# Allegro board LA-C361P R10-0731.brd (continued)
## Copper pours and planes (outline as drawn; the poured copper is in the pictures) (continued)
U2_PHASE1 on IN1 (solid shape): 172.31,105.96 172.31,105.64 172.05,105.39 170.15,105.39 169.96,105.58 169.96,105.95 170.1,106.09 172.18,106.09
U2_PHASE1 on IN1 (solid shape): 174.85,111.42 174.85,110.86 174.69,110.7 173.85,110.7 173.61,110.94 173.1,110.94 172.87,110.71 172.87,110.02 172.77,109.91 171.95,109.91 171.83,110.03 171.83,111.07 172.47,111.71 174.56,111.71
U2_PHASE2 on BOTTOM (solid shape): 176.02,119.13 176.02,118.31 175.83,118.12 174.24,118.12 173.99,118.37 173.99,119.07 174.18,119.26 175.9,119.26
U2_PHASE2 on BOTTOM (solid shape): 171.48,111.5 171.48,109.9 171.3,109.73 170.87,109.73 170.26,109.12 170.26,108.86 170.16,108.76 169.22,108.76 169.17,108.81 169.17,108.96 169.8,109.6 169.8,110.21 170.24,110.64 170.24,111.63 170.31,111.71 171.28,111.71
U2_PHASE2 on IN6 (solid shape): 171.36,111.35 171.36,110.5 171.15,110.3 170.33,110.3 170.18,110.45 170.18,111.33 170.37,111.51 171.2,111.51
U2_PHASE2 on IN6 (solid shape): 176.2,118.65 176.2,118.4 175.71,117.91 175.38,117.91 175.09,118.2 174.54,118.2 174,118.74 174,119 174.29,119.29 175.56,119.29
U2_PHASE3 on BOTTOM (solid shape): 175.73,103.65 175.73,103.35 175.51,103.13 173.8,103.13 173.61,103.32 173.61,103.67 173.8,103.86 175.51,103.86
U2_PHASE3 on BOTTOM (solid shape): 172.79,100.59 172.79,99.63 172.91,99.51 172.91,98.2 172.85,98.14 172.7,98.14 172.64,98.19 172.64,99.02 172.34,99.32 172.09,99.32 171.77,99.64 171.77,100.54 171.84,100.61 172.77,100.61
U2_PHASE3 on IN6 (solid shape): 174.75,103.77 174.75,103.26 174.53,103.04 173.58,103.04 172.72,102.18 172.72,99.77 172.95,99.54 172.95,99.21 172.74,99.01 171.9,99.01 171.7,99.2 171.7,102.82 172.78,103.89 174.63,103.89
U2_UGATE1 on BOTTOM (solid shape): 168.61,106.12 168.61,105.1 168.81,104.9 168.81,103.96 168.74,103.88 168.43,103.88 168.33,103.99 168.33,106.12 168.41,106.2 168.53,106.2
U2_UGATE1 on BOTTOM (solid shape): 175.79,109.93 175.79,109.51 175.63,109.36 175.07,109.36 174.56,108.85 174.18,108.85 174.05,108.97 174.05,109.83 174.33,110.1 175.62,110.1
U2_UGATE1 on IN1 (solid shape): 175.01,109.86 175.01,108.2 174.89,108.09 174.14,108.09 174,108.23 174,109.85 174.15,109.99 174.88,109.99
U2_UGATE1 on IN1 (solid shape): 169.01,104.97 169.01,104.34 169.18,104.16 169.59,104.16 169.71,104.05 169.71,103.3 169.53,103.12 168.68,103.12 168.31,103.49 168.31,104.92 168.43,105.04 168.94,105.04
U2_UGATE2 on BOTTOM (solid shape): 175.99,117.39 175.99,116.94 175.83,116.79 174.12,116.79 173.93,116.98 173.93,117.42 174.05,117.55 175.83,117.55
U2_UGATE2 on BOTTOM (solid shape): 168.74,111.43 168.74,110.21 168.61,110.08 168.61,109.17 168.53,109.09 168.41,109.09 168.33,109.17 168.33,110.46 168.26,110.54 168.26,111.38 168.38,111.5 168.66,111.5
U2_UGATE2 on IN6 (solid shape): 175.01,117.67 175.01,116.91 174.88,116.79 173.23,116.79 173.23,117.8 174.88,117.8
U2_UGATE2 on IN6 (solid shape): 169.8,112.45 169.8,111.81 169.26,111.27 169.26,110.76 168.91,110.41 168.33,110.41 168.15,110.59 168.15,111.88 168.83,112.56 169.69,112.56
U2_UGATE3 on BOTTOM (solid shape): 173.42,100.11 173.42,99.89 173.61,99.7 173.61,99.2 173.42,99.01 173.42,98.22 173.34,98.14 173.18,98.14 173.1,98.22 173.1,99.51 172.92,99.69 172.92,100.09 173.03,100.2 173.33,100.2
U2_UGATE3 on BOTTOM (solid shape): 175.2,102.62 175.52,102.62 175.72,102.42 175.72,102.07 175.51,101.86 174.88,101.86 174.56,102.18 173.74,102.18 173.62,102.29 173.62,102.76 173.74,102.88 174.95,102.88
U2_UGATE3 on IN6 (solid shape): 174.75,102.75 174.75,100.08 173.8,99.13 173.27,99.13 173.12,99.28 173.12,99.67 172.93,99.86 172.93,100.06 173.61,100.74 173.61,102.75 173.74,102.88 174.63,102.88
UG_3V on TOP (solid shape): 330.69,22.61 330.69,20.92 330.6,20.84 330.07,20.84 329.88,21.03 329.88,22.61 330.01,22.74 330.55,22.74
UG_3V on TOP (solid shape): 343.7,22.26 343.7,21.33 343.66,21.29 343.55,21.29 343.45,21.39 343.45,22.01 343.35,22.11 343.09,22.11 342.46,22.74 342.46,22.93 342.58,23.06 342.9,23.06
UG_3V on IN1 (solid shape): 331.92,22.55 331.92,21.6 331.79,21.47 329.88,21.47 329.82,21.54 329.82,22.74 330.01,22.93 331.53,22.93
UG_3V on IN1 (solid shape): 343.47,23.25 343.47,22.23 343.35,22.11 342.77,22.11 341.76,23.12 341.76,23.44 342.33,24.01 342.71,24.01
UG_5V on TOP (solid shape): 332.3,10.99 332.3,9.98 332.11,9.79 331.03,9.79 330.84,9.98 330.84,10.99 330.96,11.12 332.17,11.12
UG_5V on TOP (solid shape): 343.71,19.28 343.71,18.37 343.63,18.3 342.33,18.3 342.27,18.36 342.27,18.68 342.46,18.87 343.41,18.87 343.47,18.93 343.47,19 343.47,19 343.47,19.25 343.53,19.31 343.68,19.31
UG_5V on IN1 (solid shape): 333.63,11.18 333.44,10.99 333.19,10.99 332.11,9.91 331.66,9.91 331.47,10.11 331.47,11.25 332.11,11.88 333.63,11.88
UG_5V on IN1 (solid shape): 344.3,17.92 344.3,17.15 343.98,16.84 343.73,16.84 342.71,17.85 342.52,17.85 342.2,18.17 342.2,18.61 342.39,18.8 343.41,18.8
VCORE_B+ on TOP (solid shape): 143.13,106.56 143.13,105.67 142.88,105.42 142.11,105.42 141.86,105.67 141.86,106.56 141.99,106.69 143,106.69
VCORE_B+ on TOP (solid shape): 140.21,119.95 140.21,117.07 140.34,116.94 140.75,116.94 140.93,116.76 140.93,114.67 140.63,114.37 139.25,114.37 138.79,114.83 138.79,116.91 138.55,117.15 137.85,117.15 137.35,117.65 137.35,119.89 137.77,120.31 139.85,120.31
VCORE_B+ on TOP (solid shape): 140.08,112.78 140.08,111.19 140.85,110.43 140.85,108.32 140.82,108.29 140.82,107.9 140.74,107.82 139.32,107.82 138.69,108.46 138.69,110.24 138.59,110.34 138.59,112.64 138.77,112.82 138.9,112.81 139.02,112.86 140.01,112.86
VCORE_B+ on TOP (solid shape): 162.18,118.37 162.18,117.17 161.99,116.98 161.23,116.98 160.97,116.72 159.8,116.72 159.15,116.08 159.15,115.62 159,115.46 156.33,115.46 156.21,115.58 156.21,116.47 156.08,116.59 155.45,116.59 155.32,116.72 155.32,117.1 155.68,117.46 156.49,117.46 157.4,118.37 158.94,118.37 159.26,118.69 161.86,118.69
VCORE_B+ on BOTTOM (solid shape): 143.08,106.46 143.08,105.24 142.9,105.06 142.39,105.06 141.89,105.57 141.89,106.33 142.14,106.59 142.95,106.59
VCORE_B+ on BOTTOM (solid shape): outline of 140 points within 126.39,107.11 140.91,119.39
VCORE_B+ on IN6 (solid shape): 162.43,118.5 162.43,117.74 161.84,117.14 161.76,117.14 161.7,117.08 161.49,117.08 160.68,116.26 159.64,116.26 158.85,115.48 156.19,115.48 155.98,115.68 155.98,116.9 156.19,117.1 158.6,117.1 159.06,117.56 159.06,118.7 159.21,118.86 162.08,118.86
VCORE_B+ on IN6 (solid shape): 140.18,119.08 140.18,117.97 140.84,117.31 140.84,114.46 140.67,114.28 140.44,114.28 140.36,114.21 140.36,113.37 140.3,113.17 140.36,112.96 140.36,112.86 140.46,112.76 140.46,112.68 140.21,112.43 140.21,111.44 140.84,110.8 140.84,108.09 140.56,107.81 139.62,107.81 139.32,108.11 139.32,110.58 138.91,110.98 138.91,112.12 139.94,113.15 139.94,113.31 140.08,113.45 140.08,114.21 139.98,114.31 139.57,114.31 139.4,114.49 139.4,116.37 139.45,116.42 139.45,116.62 138.71,117.36 138.23,117.36 137.54,118.04 137.54,119.11 137.8,119.36 139.9,119.36
VCORE_B+ on BOTTOM: 156.05,115.45 156.02,115.48 156.02,115.9 155.93,115.99 155.39,115.99 155.3,116.07 155.3,116.19 155.39,116.28 155.96,116.28 156.03,116.35 156.03,116.97 156.06,117 158.62,117 159.26,117.64 159.26,118.07 159.54,118.35 162.33,118.35 162.43,118.25 162.43,117.36 162.12,117.04 161.48,117.04 161.27,116.82 161.26,116.82 160.64,116.2 159.62,116.2 159.04,115.62 159.04,115.48 159.02,115.45
VCORE_B+ on IN4: outline of 236 points within 136.91,105.47 162.37,119.64
VSB_N_001 on TOP: 30.74,17.53 31.56,17.53 31.81,17.28 31.81,16.52 31.94,16.39 32.58,16.39 32.7,16.26 32.7,16.01 32.89,15.82 32.89,15.5 32.77,15.38 32.01,15.38 30.86,16.52 30.74,16.52 30.67,16.58 30.67,17.47
N13272521 on TOP (solid shape): 108.84,61.48 108.84,60.46 108.65,60.27 106.81,60.27 106.68,60.4 106.68,61.03 106.74,61.1 107.63,61.1 108.08,61.54 108.78,61.54
N17034092 on TOP (solid shape): 341.2,22.23 341.2,21.57 341.22,21.57 341.65,21.14 342.04,21.14 342.34,20.84 343.35,20.84 343.41,20.78 343.41,20.64 343.37,20.6 342.31,20.6 342.21,20.7 342.07,20.7 342.07,20.7 341.12,20.7 341.08,20.66 340.32,20.66 340.22,20.76 340.22,22.23 340.34,22.35 341.08,22.35
N19849916 on TOP (solid shape): 244.92,56.27 244.92,55.44 244.86,55.38 242.57,55.38 242.44,55.51 242.44,56.27 242.57,56.4 244.79,56.4
N19912586 on TOP (solid shape): 185.6,117.76 185.6,114.69 185.22,114.31 182.25,114.31 181.67,114.88 181.67,116.59 181.77,116.69 181.77,117.26 181.99,117.48 182.88,117.48 183.64,118.25 185.12,118.25
N19912586 on BOTTOM (solid shape): 186.23,118.65 186.23,112.99 185.6,112.35 184,112.35 183.36,112.99 183.36,113.64 182.75,114.25 180.56,114.25 180.44,114.37 180.44,117.36 180.63,117.55 182.91,117.55 183.22,117.86 183.24,117.86 183.29,117.92 183.29,118.68 183.57,118.96 185.93,118.96
N19912586 on IN1 (solid shape): 186.21,118.65 186.21,113.04 185.55,112.38 184,112.38 183.38,113 183.38,113.27 183.36,113.28 183.36,113.65 182.75,114.26 180.62,114.26 180.47,114.41 180.47,117.33 180.67,117.53 182.53,117.53 183.26,118.27 183.26,118.65 183.64,119.03 185.83,119.03
N19912586 on IN2 (solid shape): 186.21,118.68 186.21,112.91 185.62,112.33 184.05,112.33 183.39,112.99 183.39,113.57 182.7,114.26 180.6,114.26 180.42,114.44 180.42,117.33 180.62,117.53 182.86,117.53 183.29,117.97 183.29,118.68 183.57,118.96 185.93,118.96
N19912586 on IN4 (solid shape): 186.26,118.65 186.26,112.99 185.62,112.35 183.97,112.35 183.36,112.96 183.36,113.62 182.73,114.26 180.57,114.26 180.44,114.39 180.44,117.33 180.65,117.53 182.86,117.53 183.26,117.94 183.29,117.94 183.29,118.7 183.54,118.96 185.95,118.96
N19912586 on IN5 (solid shape): 186.23,118.65 186.23,112.99 185.6,112.35 184,112.35 183.34,113.01 183.34,113.65 182.73,114.26 180.6,114.26 180.42,114.44 180.42,117.31 180.65,117.53 182.86,117.53 183.29,117.97 183.29,118.68 183.57,118.96 185.93,118.96
N48708347 on BOTTOM (solid shape): 283.53,29.09 283.53,26.87 283.47,26.81 282.77,26.81 282.7,26.87 282.7,29.03 282.83,29.16 283.47,29.16
N52699143 on TOP (solid shape): 33.66,5.03 33.66,2.2 33.37,1.91 32.64,1.91 32.32,2.23 32.32,5.03 32.51,5.22 33.47,5.22
N110703687 on TOP (solid shape): 181.23,109.48 181.23,107.9 181.02,107.69 180.17,107.69 179.9,107.96 178.82,107.96 178.75,108.02 178.75,109.04 178.82,109.1 179.64,109.1 180.09,109.55 181.17,109.55
N110833422 on TOP (solid shape): 185.52,109.66 185.52,106.13 185.22,105.83 182.65,105.83 181.45,107.03 181.45,107.93 181.42,107.96 181.42,109.85 181.71,110.14 185.04,110.14
N110833422 on BOTTOM (solid shape): 186.27,111.2 186.27,104.8 185.54,104.06 183.17,104.06 182.67,104.56 182.67,105.51 181.43,106.75 180.44,106.75 180.31,106.88 180.31,109.86 180.5,110.05 182.75,110.05 184.21,111.51 185.95,111.51
N110833422 on IN1 (solid shape): 186.26,111.08 186.26,104.89 186.25,104.87 186.25,104.77 185.6,104.12 183.44,104.12 182.83,104.73 182.83,105.6 181.66,106.77 180.62,106.77 180.39,106.99 180.39,109.91 180.54,110.07 182.78,110.07 184.07,111.36 185.98,111.36
N110833422 on IN2 (solid shape): 186.26,111.08 186.26,104.89 186.25,104.87 186.25,104.77 185.6,104.12 183.44,104.12 182.83,104.73 182.83,105.6 181.66,106.77 180.62,106.77 180.39,106.99 180.39,109.91 180.54,110.07 182.78,110.07 184.07,111.36 185.98,111.36
N110833422 on IN4 (solid shape): 186.26,111.08 186.26,104.89 186.25,104.87 186.25,104.77 185.6,104.12 183.44,104.12 182.83,104.73 182.83,105.6 181.66,106.77 180.62,106.77 180.39,106.99 180.39,109.91 180.54,110.07 182.78,110.07 184.07,111.36 185.98,111.36
N110833422 on IN5 (solid shape): 186.26,111.08 186.26,104.89 186.25,104.87 186.25,104.77 185.6,104.12 183.44,104.12 182.83,104.73 182.83,105.6 181.66,106.77 180.62,106.77 180.39,106.99 180.39,109.91 180.54,110.07 182.78,110.07 184.07,111.36 185.98,111.36
N110836828 on TOP (solid shape): 180.91,101.8 180.91,100.21 180.72,100.02 179.96,100.02 179.58,100.4 178.75,100.4 178.63,100.53 178.63,101.42 178.75,101.55 179.45,101.55 179.83,101.93 180.79,101.93
N110836908 on TOP (solid shape): 185.59,102.54 185.59,100.38 185.29,100.08 181.67,100.08 181.48,100.28 181.48,101.74 181.5,101.75 181.5,102.48 181.79,102.78 185.34,102.78
N110836908 on BOTTOM (solid shape): 186.28,103.03 186.28,99.91 184.74,98.36 184.74,98.03 184.68,97.98 181.92,97.98 180.57,99.32 180.34,99.32 180.21,99.45 180.21,102.43 180.4,102.62 182.58,102.62 183.36,103.41 185.9,103.41
N110836908 on IN1 (solid shape): 186.18,102.98 186.18,99.81 184.81,98.43 181.51,98.43 180.32,99.63 180.32,102.35 180.49,102.52 182.5,102.52 183.34,103.36 185.8,103.36
N110836908 on IN2 (solid shape): 186.18,102.98 186.18,99.81 184.81,98.43 181.51,98.43 180.32,99.63 180.32,102.35 180.49,102.52 182.5,102.52 183.34,103.36 185.8,103.36
N110836908 on IN4 (solid shape): 186.18,102.98 186.18,99.81 184.81,98.43 181.51,98.43 180.32,99.63 180.32,102.35 180.49,102.52 182.5,102.52 183.34,103.36 185.8,103.36
N110836908 on IN5 (solid shape): 186.18,102.98 186.18,99.81 184.81,98.43 181.51,98.43 180.32,99.63 180.32,102.35 180.49,102.52 182.5,102.52 183.34,103.36 185.8,103.36
N110935541 on BOTTOM (solid shape): 171.25,102.95 171.25,102.19 171.23,102.17 168.92,102.17 168.9,102.19 168.9,102.83 169.11,103.03 171.17,103.03
N110936515 on BOTTOM (solid shape): 171.51,113.04 171.51,112.4 171.32,112.21 169.1,112.21 168.95,112.37 168.95,113.09 169.09,113.23 171.32,113.23
N110936976 on BOTTOM (solid shape): 174.5,101.99 174.5,101.35 174.44,101.29 171.83,101.29 171.77,101.35 171.77,101.99 171.83,102.05 174.44,102.05
N111796536 on TOP (solid shape): 312.6,33.87 312.6,33.22 311.28,31.9 309.88,31.9 309.86,31.92 309.86,32.83 309.89,32.86 310.85,32.86 311.93,33.95 312.51,33.95
N111796622 on TOP (solid shape): 312.64,37.46 312.64,36.53 312.59,36.49 312.59,35.35 312.54,35.3 311.63,35.3 311.56,35.37 311.56,36.25 311.9,36.59 311.9,37.42 312.02,37.54 312.56,37.54
N116494866 on TOP (solid shape): 237.51,53.23 237.55,53.15 237.55,51.29 237.4,51.14 236.39,51.14 235.87,51.66 235.14,51.66 235.01,51.79 235.01,52.96 235.05,53.04 235.14,53.06 235.53,52.99 235.92,52.96 236.68,53.03 237.41,53.24
N116496514 on TOP (solid shape): 181.42,116.72 181.42,115.13 181.23,114.94 180.47,114.94 180.15,115.26 179.52,115.26 179.32,115.45 179.32,116.4 179.39,116.47 180.02,116.47 180.4,116.85 181.29,116.85
N119009632 on BOTTOM (solid shape): 17.75,69.7 17.75,69.33 17.48,69.06 17.48,68.58 17.04,68.14 16.75,68.14 16.59,68.29 16.59,69.61 16.81,69.83 17.62,69.83
N119942216 on BOTTOM (solid shape): 27.7,79.11 27.7,78.09 27.27,77.65 27.27,76.7 26.59,76.01 26.59,75.5 26.52,75.43 24.57,75.43 24.33,75.19 24.33,70.28 24.2,70.14 20.46,70.14 20.4,70.2 20.4,76.69 24.64,76.69 24.64,76.64 24.65,76.59 24.66,76.54 24.69,76.49 24.72,76.44 24.75,76.4 24.79,76.37 24.84,76.34 24.89,76.33 24.94,76.31 25,76.31 25.05,76.31 25.1,76.33 25.15,76.34 25.2,76.37 25.24,76.4 25.27,76.44 25.3,76.49 25.33,76.54 25.34,76.59 25.35,76.64 25.35,76.69 25.34,76.75 25.33,76.8 25.3,76.84 25.27,76.89 25.24,76.93 25.2,76.96 25.15,76.99 25.1,77.01 25.05,77.02 25,77.02 24.94,77.02 24.89,77.01 24.84,76.99 24.79,76.96 24.75,76.93 24.72,76.89 24.69,76.84 24.66,76.8 24.65,76.75 24.64,76.69 20.4,76.69 20.4,78.05 20.72,78.37 21.46,78.37 22.25,79.15 22.46,79.15 22.48,79.18 27.64,79.18
N119944438 on TOP (solid shape): 53.35,16 53.45,16 53.51,15.95 53.51,15.39 52.16,14.04 51.37,14.04 51.18,13.85 51.18,13.34 51.06,13.22 50.8,13.22 50.67,13.34 50.67,13.98 50.74,14.04 50.74,15.34 50.86,15.47 52.29,15.47 52.64,15.82 52.64,15.95 52.71,16.01 53.34,16.01
N119965248 on BOTTOM (solid shape): 27.26,68.67 27.35,68.34 27.51,68.03 27.52,68.01 27.52,67.21 27.41,67.09 27.41,66.8 27.34,66.72 27.29,66.63 27.29,66.61 27.17,66.49 25.66,66.49 24.92,65.76 24.92,64.83 24.63,64.54 23.42,64.54 22.99,64.97 22.61,64.97 22.47,65.1 22.47,65.48 22.73,65.74 23.1,65.74 24.14,66.78 24.17,66.78 24.17,66.81 24.37,67.01 24.66,67.01 24.68,67.03 24.7,67.03 24.83,67.12 24.91,67.25 24.92,67.27 25.01,67.36 25.01,67.45 26.43,67.45 26.79,67.8 26.43,68.16 25.01,68.16 25.01,68.66 25.08,68.73 27.25,68.73
N119965290 on BOTTOM (solid shape): 25.55,65.62 25.55,64.98 25.71,64.83 26.04,64.83 26.12,64.74 26.12,64.72 26.14,64.7 26.14,64.37 26.06,64.3 25.9,64.3 25.89,64.31 25.32,64.31 25.15,64.47 25.15,65.64 25.26,65.74 25.43,65.74
N120361841 on TOP (solid shape): 59.25,3.18 59.25,2.68 58.8,2.23 57.21,2.23 56.96,2.49 56.96,3.25 57.02,3.31 59.12,3.31
N120970730 on TOP (solid shape): 150.05,101.74 150.05,100.66 149.42,100.02 147,100.02 146.75,100.28 146.75,101.06 146.97,101.28 147,101.28 147.65,101.93 149.86,101.93
N120971346 on BOTTOM (solid shape): 148.34,117.96 148.34,117.69 148.54,117.48 149.23,117.48 149.29,117.42 149.29,116.47 149.1,116.28 147.26,116.28 147.11,116.42 147.11,117.97 147.23,118.09 148.21,118.09
N120971480 on TOP (solid shape): 161.8,111.71 161.8,109.67 161.56,109.43 159.95,109.43 159.83,109.55 159.83,110.5 159.96,110.63 160.78,110.63 160.85,110.69 160.85,111.64 161.04,111.83 161.67,111.83
N120976432 on TOP (solid shape): 161.49,108.77 161.49,108.59 161.52,108.59 161.65,108.47 161.65,106.83 161.35,106.54 161.27,106.54 160.48,105.75 160.48,105.7 159.61,105.7 158.62,106.69 158.62,108.09 159.51,108.97 161.29,108.97
N120976432 on BOTTOM (solid shape): 158.67,112.94 158.67,112.54 159.27,111.95 161.11,111.95 161.32,111.74 161.32,106.29 160.91,105.88 160.86,105.88 160.71,105.72 159.36,105.72 158.95,106.14 158.93,106.17 158.93,107.17 158.65,107.45 156.02,107.45 155.7,107.77 155.7,112.47 156.05,112.81 156.05,113.04 156.24,113.23 158.38,113.23
N120976432 on IN6 (solid shape): 158.7,112.91 158.7,112.53 159.26,111.97 161.16,111.97 161.32,111.82 161.32,106.28 160.94,105.9 160.86,105.9 160.61,105.65 159.51,105.65 158.98,106.18 158.98,107.15 158.67,107.45 156.03,107.45 155.73,107.76 155.73,112.51 156.19,112.96 156.19,113.06 156.34,113.22 158.4,113.22
N120977691 on BOTTOM (solid shape): 146.56,117.93 146.56,116.44 146.56,116.37 147.24,115.68 149.25,115.68 149.4,115.53 149.4,113.78 149.05,113.42 147.96,113.42 147.73,113.19 147.73,112.33 148.34,111.72 148.34,111.31 148.03,111.01 145.06,111.01 144.97,111.1 144.97,113.93 144.4,114.5 143.19,114.5 143.13,114.56 143.13,116.59 143.13,116.62 143.17,116.66 143.97,116.66 144.46,117.15 144.46,117.99 144.53,118.06 146.43,118.06
N120977691 on IN6 (solid shape): 146.56,117.86 146.56,116.34 147.17,115.73 149.33,115.73 149.53,115.53 149.53,113.75 149.2,113.42 148.24,113.42 147.88,113.06 147.88,112.38 148.44,111.82 148.44,111.39 148.01,110.96 145.16,110.96 144.96,111.16 144.96,113.72 144.98,113.75 144.98,113.9 144.37,114.51 143.26,114.51 143.1,114.66 143.1,116.49 143.33,116.72 144.1,116.72 144.48,117.1 144.48,117.76 144.43,117.81 144.43,117.89 144.58,118.04 146.38,118.04
N121616264 on TOP (solid shape): 222.67,11.48 222.67,9.4 222.6,9.33 221.94,9.33 221.69,9.58 221.69,11.58 221.74,11.63 222.52,11.63
N121617759 on TOP: 238.69,5.15 238.2,5.63 238.2,7.37 238.25,7.43 239.71,7.43 239.8,7.34 239.8,6.83 240.89,5.74 240.89,5.2 240.84,5.15
N121617766 on TOP (solid shape): 244.3,7.39 244.3,5.5 243.96,5.16 242.31,5.16 242.27,5.2 242.27,5.86 242.72,6.32 242.72,7.4 242.84,7.51 244.17,7.51
N121795600 on TOP (solid shape): 145.82,104.02 148.53,104.02 148.65,103.89 148.65,102.74 148.43,102.51 148.41,102.51 148.15,102.24 147.52,102.24 146.79,101.51 145.52,101.51 144.93,102.09 144.93,103.97 145.24,104.28 145.57,104.28
N121795600 on BOTTOM (solid shape): 148.97,110.02 148.97,106.1 148.82,105.95 147.86,105.95 147.73,105.83 147.73,104.89 147.91,104.71 148.57,104.71 148.97,104.3 148.97,101.96 148.49,101.48 145.75,101.48 144.97,102.26 144.97,106.94 143.96,107.96 143.13,107.96 143.07,108.02 143.07,110.18 143.08,110.2 144.63,110.2 144.9,110.47 148.51,110.47
N121795600 on IN6 (solid shape): 149.05,110.14 149.05,106.1 148.87,105.93 148.21,105.93 147.8,105.52 147.8,104.96 148.06,104.71 148.59,104.71 148.95,104.35 148.95,102.07 148.51,101.63 145.8,101.63 145.78,101.65 145.56,101.65 144.86,102.35 144.86,107.1 143.99,107.96 143.08,107.96 143,108.04 143,110.02 143.18,110.19 144.58,110.19 144.96,110.58 148.62,110.58
N121994849 on TOP (solid shape): 219.66,47.28 220.56,47.28 220.6,47.24 220.6,46.62 220.54,46.55 218.38,46.55 218.31,46.62 218.31,47.38 218.38,47.44 219.5,47.44
N122017154 on BOTTOM (solid shape): 138.69,111.9 138.69,110.63 139.07,110.24 139.07,109.86 138.56,109.86 138.05,110.37 138.05,111.39 137.8,111.64 137.29,111.64 137.16,111.77 137.16,112.28 138.3,112.28
N122018016 on BOTTOM (solid shape): 139.17,116.47 139.17,116.29 139.14,116.26 138.56,116.26 138.3,116.52 138.3,116.67 137.92,117.05 137.52,117.05 137.39,117.18 137.39,117.64 137.44,117.69 137.95,117.69
N122018494 on BOTTOM (solid shape): 159.51,119.01 159.51,118.63 159.01,118.12 159.01,117.87 158.56,117.42 158.56,117.34 158.4,117.18 158.1,117.18 157.98,117.31 157.98,117.67 158.88,118.58 158.88,119.01 158.95,119.08 159.44,119.08
N122528028 on TOP: 230.46,50.28 231.39,50.28 231.47,50.2 231.47,48.43 231.04,48 228.74,48 228.06,48.68 228.06,50.15 228.35,50.44 228.73,50.44 229.25,49.92 230.1,49.92
N122536166 on TOP (solid shape): 28.35,67.22 28.35,67.03 28.53,66.86 28.53,65.7 28.58,63.96 28.71,62.24 28.72,62.21 28.72,61.74 28.58,61.6 27.66,61.6 27.06,62.21 27.06,67.2 27.2,67.34 27.56,67.34 27.66,67.45 28.13,67.45
N122536166 on BOTTOM (solid shape): 28.33,67.18 28.33,67.08 28.53,66.88 28.53,65.7 28.58,64.01 28.71,62.33 28.71,62.3 28.71,61.89 28.45,61.63 28.08,61.63 27.46,62.25 27.46,66.26 27.43,66.28 27.43,66.61 27.53,66.71 27.53,67.04 27.69,67.19 27.69,67.32 27.81,67.45 28.07,67.45
N122719762 on BOTTOM (solid shape): 18.96,60.85 18.96,60.66 18.05,59.75 18.05,57.23 17.96,57.14 17.41,57.14 17.26,57.29 17.26,58.65 17.08,58.83 17.08,60.11 17.53,60.56 17.53,60.75 17.77,60.98 18.83,60.98
N122728389 on TOP (solid shape): 25.66,14.86 25.66,11.13 25.06,10.54 25.06,9.25 24.06,8.24 22.5,8.24 21.86,7.61 21.86,6.55 21.81,6.51 20.57,6.51 20.5,6.58 20.5,7.2 22.14,8.84 23.39,8.84 23.82,9.27 23.82,10.83 24.45,11.46 24.45,14.79 24.67,15.01 25.5,15.01
N122729223 on TOP (solid shape): 27.5,14.68 27.5,13.47 28,12.96 28.89,12.96 30.01,11.85 30.01,10.25 29.89,10.13 28.87,10.13 28.2,10.8 26.16,10.8 25.91,11.06 25.91,14.87 26.04,14.99 27.18,14.99
N122754331 on TOP (solid shape): 131.99,67.26 131.99,66.61 131.93,66.54 129.5,66.54 129.41,66.63 129.41,67.24 129.53,67.36 131.89,67.36
N122755391 on BOTTOM (solid shape): 185.93,86.46 186.1,86.46 186.27,86.29 186.27,83.68 185.68,83.08 185.3,83.08 184.88,82.66 184.42,82.66 184.28,82.52 184.28,82.08 184.12,81.92 183.55,81.92 183.36,82.12 183.36,83.06 183.47,83.16 183.67,83.16 184.88,84.37 184.88,86.28 185.06,86.46 185.93,86.46
N122762967 on TOP (solid shape): 229.88,60.49 230.56,60.49 230.63,60.41 230.63,59.66 230.53,59.56 230.45,59.56 229.89,59 228.26,59 228.14,59.11 228.14,60.51 228.21,60.58 229.79,60.58
N122912247 on TOP (solid shape): 182.18,82.06 182.18,81.86 181.96,81.64 181.96,81.55 181.95,81.54 181.94,81.44 181.95,81.34 181.96,81.34 181.96,81.25 182.54,80.66 182.54,79.49 182.36,79.3 181.79,79.3 181.7,79.4 181.7,80.27 181.51,80.46 181.16,80.46 181.03,80.59 181.03,81.28 180.5,81.81 180.5,82.11 180.64,82.25 181.98,82.25
N123037911 on BOTTOM: 202.59,55.5 202.25,55.16 201.08,55.16 200.85,55.39 200.85,56 201.11,56.26 201.11,57.63 202.05,58.56 202.29,58.56 202.49,58.76 203.9,58.76 203.96,58.7 203.96,57.94 203.66,57.64 203.18,57.64 202.59,57.05
N123983992 on TOP (solid shape): 114.12,69.63 114.12,67.95 113.56,67.4 111.2,67.4 110.87,67.73 110.87,68.42 110.94,68.48 110.94,69.8 111.19,70.05 113.7,70.05
N123983992 on BOTTOM (solid shape): 108.97,74.75 109.92,74.75 110.3,74.37 113.03,74.37 113.04,74.36 114.24,74.36 114.92,73.68 114.92,71.37 114.53,70.98 113.44,70.98 113.35,70.89 113.35,69.85 113.39,69.81 114.56,69.81 114.91,69.45 114.91,66.96 114.78,66.84 111.74,66.84 110.49,68.08 110.49,71.64 109.67,72.46 108.97,72.46 108.82,72.61 108.82,74.68 108.89,74.75 108.97,74.75
N123983992 on IN3 (solid shape): 110.36,74.38 114.3,74.38 114.99,73.69 114.99,71.33 114.61,70.95 113.56,70.95 113.34,70.72 113.34,69.94 113.49,69.78 114.53,69.78 114.91,69.4 114.91,67.04 114.71,66.84 111.76,66.84 110.52,68.08 110.52,71.71 109.7,72.53 108.92,72.53 108.79,72.65 108.79,74.68 108.84,74.74 110.01,74.74
N123983992 on IN4 (solid shape): 110.36,74.38 114.3,74.38 114.99,73.69 114.99,71.33 114.61,70.95 113.56,70.95 113.34,70.72 113.34,69.94 113.49,69.78 114.53,69.78 114.91,69.4 114.91,67.04 114.71,66.84 111.76,66.84 110.52,68.08 110.52,71.71 109.7,72.53 108.92,72.53 108.79,72.65 108.79,74.68 108.84,74.74 110.01,74.74
N123983992 on IN6 (solid shape): 110.36,74.38 114.3,74.38 114.99,73.69 114.99,71.33 114.61,70.95 113.56,70.95 113.34,70.72 113.34,69.94 113.49,69.78 114.53,69.78 114.91,69.4 114.91,67.04 114.71,66.84 111.76,66.84 110.52,68.08 110.52,71.71 109.7,72.53 108.92,72.53 108.79,72.65 108.79,74.68 108.84,74.74 110.01,74.74
N123984012 on TOP (solid shape): 107.89,96.81 107.89,93.61 107.51,93.23 105.73,93.23 105.54,93.42 105.54,93.42 105.48,93.48 105.48,96.34 106.21,97.07 107.62,97.07
N123984012 on BOTTOM (solid shape): 108.91,98.06 109.66,98.06 109.66,98.6 110.11,98.6 110.11,98.07 110.81,98.07 110.82,98.06 111.23,98.06 111.41,97.88 111.41,96.85 111.22,96.66 108.46,96.66 108.14,96.34 108.14,91.64 108.08,91.58 107.63,91.58 107.55,91.66 107.55,92.15 107.33,92.37 106.56,92.37 106.47,92.46 106.47,92.97 106.18,93.26 105.62,93.26 105.48,93.4 105.48,94.14 105.28,94.34 104.84,94.34 104.79,94.39 104.79,95.65 104.97,95.83 106.1,95.83 106.55,96.29 106.55,97.1 107.51,98.06 108.46,98.06 108.46,98.6 108.91,98.6
N123984061 on BOTTOM (solid shape): 113.29,96.05 113.29,95.7 113.48,95.51 113.86,95.51 113.98,95.39 113.98,95.13 113.92,95.07 112.71,95.07 112.6,95.18 112.6,96.08 112.72,96.2 113.14,96.2
N123984061 on BOTTOM (solid shape): 109.46,94.2 109.46,90.56 109.41,90.51 109.41,87.07 108.84,86.5 104.78,86.5 104.63,86.65 104.63,88 104.77,88.15 106.74,88.15 107.06,88.46 107.06,90.43 107.7,91.07 108.08,91.07 108.4,91.39 108.4,94.19 108.42,94.21 109.45,94.21
N123984061 on IN6 (solid shape): 113.54,96.66 113.54,95.45 113.16,95.07 112.71,95.07 112.59,95.2 112.59,96.07 112.31,96.35 112.31,96.9 112.58,97.17 113.02,97.17
N123984061 on IN6 (solid shape): 109.48,92.15 109.48,90.94 109.35,90.81 108.21,90.81 108.14,90.88 108.14,91.64 108.52,92.02 108.52,92.21 108.65,92.34 109.28,92.34
N123984063 on BOTTOM (solid shape): 107.38,92.07 107.38,91.13 107.32,91.07 106.43,91.07 106.3,91.19 106.3,92.02 106.47,92.19 107.26,92.19
N123984063 on BOTTOM (solid shape): 117.41,95.89 117.41,95.26 117.35,95.2 116.27,95.2 116.14,95.07 115.44,95.07 115.38,95.13 115.38,95.83 115.51,95.96 117.35,95.96
N123984063 on IN6 (solid shape): 107.51,91.58 107.51,90.05 107.5,90.05 107.5,89.87 107.25,89.62 107.06,89.62 107.06,89.67 106.36,90.37 106.36,91.64 106.43,91.7 107.38,91.7
N123984063 on IN6 (solid shape): 117.41,95.89 117.41,95.26 117.35,95.2 116.4,95.2 116.21,95 116.21,94.24 116.02,94.05 115.7,94.05 115.41,94.34 115.41,95.61 115.83,96.02 117.29,96.02
N123984101 on BOTTOM (solid shape): 104.87,76.49 104.87,74.41 104.79,74.33 104.27,74.33 104.13,74.48 104.13,76.32 104.4,76.59 104.78,76.59
N123984161 on BOTTOM (solid shape): 106.11,91.45 106.11,90.75 106.49,90.37 106.49,89.35 106.38,89.24 104.76,89.24 104.65,89.35 104.65,91.39 104.84,91.57 105.99,91.57
N123984183 on TOP (solid shape): 115.55,81.8 115.55,80.32 115.11,79.89 110.72,79.89 110.43,80.18 110.43,81.8 110.56,81.93 110.56,81.97 111.91,83.32 114.02,83.32
N123984183 on BOTTOM (solid shape): 115.83,84.01 115.83,83.32 115.65,83.14 114.38,83.14 114.25,83.02 114.25,82.15 114.51,81.9 115.65,81.9 115.83,81.72 115.83,79.82 115.65,79.64 110.94,79.64 110.57,80 109.81,80 109.54,80.27 109.54,82.37 109.73,82.56 110.57,82.56 111.06,83.05 111.06,83.83 111.32,84.08 112.52,84.08 113.01,84.57 115.27,84.57
N123984183 on IN3 (solid shape): 115.83,84.01 115.83,83.32 115.65,83.14 114.38,83.14 114.25,83.02 114.25,82.15 114.51,81.9 115.24,81.9 115.52,81.62 115.52,79.79 115.37,79.64 110.94,79.64 110.57,80 109.81,80 109.54,80.27 109.54,82.37 109.73,82.56 110.57,82.56 111.06,83.05 111.06,83.83 111.32,84.08 112.52,84.08 113.01,84.57 115.27,84.57
N123984183 on IN4 (solid shape): 115.83,84.01 115.83,83.32 115.65,83.14 114.38,83.14 114.25,83.02 114.25,82.15 114.51,81.9 115.24,81.9 115.52,81.62 115.52,79.79 115.37,79.64 110.94,79.64 110.57,80 109.81,80 109.54,80.27 109.54,82.37 109.73,82.56 110.57,82.56 111.06,83.05 111.06,83.83 111.32,84.08 112.52,84.08 113.01,84.57 115.27,84.57
N123984183 on IN6 (solid shape): 115.83,84.01 115.83,83.32 115.65,83.14 114.38,83.14 114.25,83.02 114.25,82.15 114.51,81.9 115.24,81.9 115.52,81.62 115.52,79.79 115.37,79.64 110.94,79.64 110.57,80 109.81,80 109.54,80.27 109.54,82.37 109.73,82.56 110.57,82.56 111.06,83.05 111.06,83.83 111.32,84.08 112.52,84.08 113.01,84.57 115.27,84.57
N123984193 on BOTTOM (solid shape): 105.16,83.19 105.33,83.19 105.64,82.89 105.64,82.03 105.55,81.94 104.9,81.94 104.65,82.19 104.65,82.69 104.52,82.81 103.76,82.81 103.67,82.9 103.67,83.36 103.89,83.57 104.78,83.57
N123984351 on BOTTOM (solid shape): 113.98,93.73 113.98,93.42 113.64,93.07 113.26,93.07 111.76,91.58 109.79,91.58 109.62,91.75 109.62,92.07 109.79,92.24 111.28,92.24 112.72,93.68 113.04,93.68 113.17,93.81 113.91,93.81
N123984423 on TOP (solid shape): 112.97,73.54 112.97,71.7 112.65,71.38 111.32,71.38 111.06,71.64 111.06,73.61 111.32,73.86 112.65,73.86
N123984459 on TOP (solid shape): 112.59,79.13 112.59,77.22 112.33,76.97 111.09,76.97 110.62,77.45 110.62,79.13 110.75,79.26 112.46,79.26
N124695548 on TOP (solid shape): 19.62,7.33 19.62,6.43 19.51,6.32 15.81,6.32 15.63,6.5 15.63,7.31 15.83,7.5 19.45,7.5
N125814267 on TOP (solid shape): 336.25,101.09 336.25,100.37 336.04,100.16 334.15,100.16 334.12,100.18 334.12,101.1 334.21,101.19 336.14,101.19
N125857121 on TOP: 44.81,29.95 43.91,29.95 43.72,29.77 43.72,28.2 43.41,27.89 43,27.89 42.67,27.56 42.67,26.93 42.95,26.65 44.45,26.65 44.59,26.79 44.59,27.59 44.9,27.91 44.9,28.33 44.84,28.39 44.84,29.93
N126088934 on TOP: 24.1,5.28 24.1,4.18 22.88,2.96 20.71,2.96 19.3,4.37 19.3,4.38 19.13,4.55 19.13,5.62 19.31,5.81 22.18,5.81 22.27,5.72 22.27,5.42 22.42,5.26 24.09,5.26
N126088934 on BOTTOM: 24.82,55.19 24.65,55.03 24.44,55.03 24.27,55.19 23.9,55.19 23.77,55.32 23.77,55.56 23.17,56.16 20.65,56.16 19.41,57.4 19.41,60.14 19.48,60.21 19.69,60.21 19.71,60.2 19.83,60.18 19.95,60.2 19.96,60.21 20.08,60.21 20.08,58.81 20.44,58.45 20.79,58.81 20.79,60.21 21.35,60.21 21.35,58.45 21.82,57.97 23.59,57.97 24.19,57.38 24.62,57.38 24.82,57.18
N126088934 on IN1: outline of 174 points within 19.2,4 32.19,57.64 ; 1 cut-out
N127291517 on BOTTOM (solid shape): 342.2,43.95 342.2,42.68 342.08,42.55 341.5,42.55 341.12,42.93 341.12,43.28 340.74,43.66 339.99,43.66 339.92,43.74 339.92,44.35 340,44.44 341.71,44.44

Small or netless copper shapes (teardrops, artwork), in the pictures only: 77 on TOP, 294 on BOTTOM, 1 on IN3, 1 on IN5, 1 on IN6

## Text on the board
Ref Des/Silkscreen Bottom: H6 | H48 | H5 | SUPPORT | DDR4 | DIMM-A | ONLY | DIMM-B
User.Comments: Issued | PROJECT | BOARD NO. | LAYER NO. | DRAW BY | Security level | Decipherment date | COMPAL ELECTRONICS. INC. | Date | LA-C361P | Confidential | COMP.SIDE | 2016-01-22 | 2016-07-30 | 2015-01-22 | 2015-07-30 | Chris_Wang | AAM00 | Win | REV:0.3(X02)
IN5: IN5
IN6: IN6
BODY_CENTER: GND | +SDC_IN | +3VALW | +1V_MPHY | +5VS | +VCCGT | +3VS | B+ | +VCC_CORE | +1.2V_DDR | +GPU_CORE | +1.35VSDGPU | +5V_CHGUSB_1
USER_PART_NUM_TOP: Issued | PROJECT | BOARD NO. | LAYER NO. | DRAW BY | Security level | Decipherment date | COMPAL ELECTRONICS. INC. | Date | LA-C361P | Confidential | COMP.SIDE | 2016-04-09 | 2015-04-10 | AAM00 | Bruce | REV:0.4(X03)
DEVICE_TYPE_TOP: Issued | PROJECT | BOARD NO. | LAYER NO. | DRAW BY | Security level | Decipherment date | COMPAL ELECTRONICS. INC. | Date | LA-C361P | Confidential | IN1 | 2016-04-09 | 2015-04-10 | AAM00 | Bruce | REV:0.4(X03)
PAGE_OUTLINE: Issued | PROJECT | BOARD NO. | LAYER NO. | DRAW BY | Security level | Decipherment date | COMPAL ELECTRONICS. INC. | Date | LA-C361P | Confidential | IN2 | 2016-04-09 | 2015-04-10 | AAM00 | Bruce | REV:0.4(X03)
User.9: Issued | PROJECT | BOARD NO. | LAYER NO. | DRAW BY | Security level | Decipherment date | COMPAL ELECTRONICS. INC. | Date | LA-C361P | Confidential | IN3 | 2016-04-09 | 2015-04-10 | AAM00 | Bruce | REV:0.4(X03)
User.10: Issued | PROJECT | BOARD NO. | LAYER NO. | DRAW BY | Security level | Decipherment date | COMPAL ELECTRONICS. INC. | Date | LA-C361P | Confidential | IN4 | 2016-04-09 | 2015-04-10 | AAM00 | Bruce | REV:0.4(X03)
User.11: Issued | PROJECT | BOARD NO. | LAYER NO. | DRAW BY | Security level | Decipherment date | COMPAL ELECTRONICS. INC. | Date | LA-C361P | Confidential | IN5 | 2016-04-09 | 2015-04-10 | AAM00 | Bruce | REV:0.4(X03)
User.12: Issued | PROJECT | BOARD NO. | LAYER NO. | DRAW BY | Security level | Decipherment date | COMPAL ELECTRONICS. INC. | Date | LA-C361P | Confidential | IN6 | 2016-04-09 | 2015-04-10 | AAM00 | Bruce | REV:0.4(X03)
User.13: Issued | PROJECT | BOARD NO. | LAYER NO. | DRAW BY | Security level | Decipherment date | COMPAL ELECTRONICS. INC. | Date | LA-C361P | SOLD.SIDE | Confidential | 2016-04-09 | 2015-04-10 | AAM00 | Bruce | REV:0.4(X03)
User.45: Width/space | 4.7 / 5.5 | 4.7/5.5 | 3.9 / 4.4 | 3.8 / 3.5 | 4/6.5 | 90 ohm | FIGURE | SIZE | 8.0 | 16.0 | 20.0 | 26.0 | 30.0 | 36.0 | 91.0 | 98.0 | 110.0 | 118.0 | 126.0 | 154.0 | 161.0 | 31.0 | 35.0 | 40.0 | 43.0 | 63.0 | 83.0 | 236.0 | 63.0x24.0 | 67.0x39.0 | 75.0x24.0 | 37.0x30.0 | 98.0x83.0 | 114.0x83.0 | DRILL CHART: TOP to BOTTOM | ALL UNITS ARE IN MILS | TOLERANCE | +3.0/-3.0 | +2.0/-2.0 | PLATED | NON-PLATED | QTY | 8200 | 12 | 19 | 2 | 18 | 4 | 1 | 8
